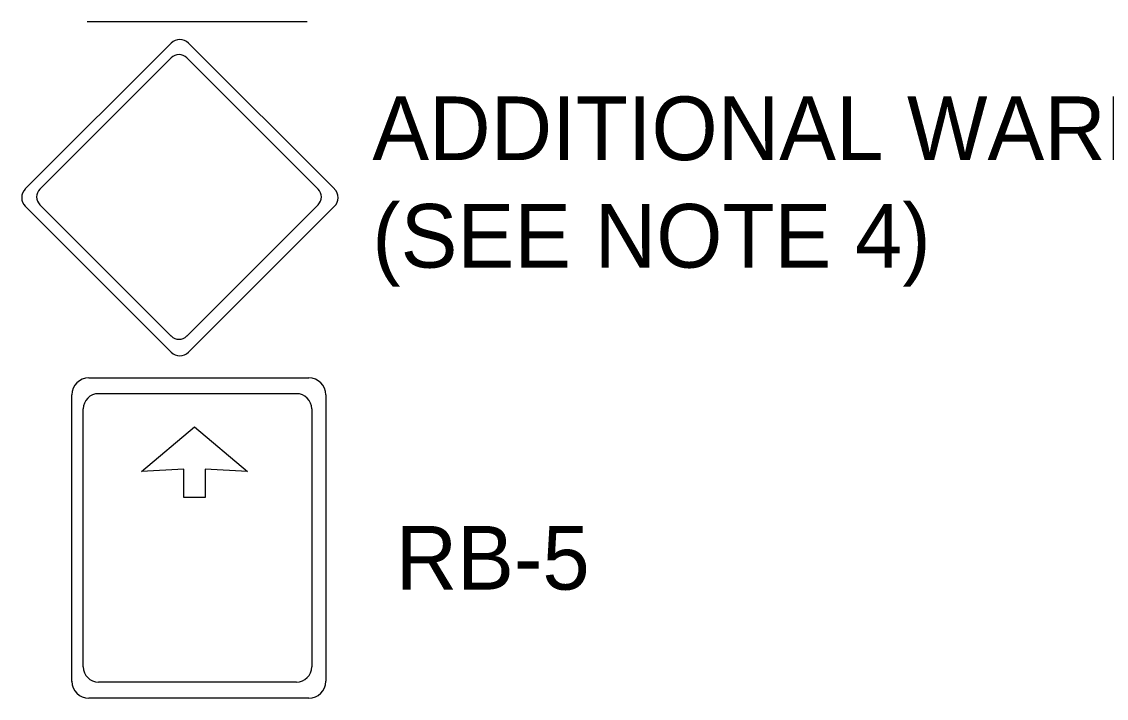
# Model space of a CAD drawing. Extents: x 1372 to 1588, y 125 to 404.
# Drawn here: x 1476.63 to 1513.7, y 179.59 to 202.73 of the extents above; entities that cross this region are included whole.
import ezdxf

# ---------------------------------------------------------------- set-up
doc = ezdxf.new("R2010")
doc.units = 0
doc.layers.add('Level 10', color=7, linetype='Continuous')
doc.layers.add('Level 44', color=7, linetype='Continuous')

msp = doc.modelspace()

# ---------------------------------------------------------------- linework, layer by layer
at = {"layer": 'Level 44'}
for p, q in [((1486.366, 202.729), (1478.871, 202.729)), ((1486.366, 202.729), (1478.871, 202.729)), ((1486.388, 202.728), (1478.872, 202.728)), ((1481.744, 201.993), (1476.75, 197.007)), ((1487.321, 197.007), (1482.334, 201.993)), ((1477.249, 197.003), (1481.744, 201.491)), ((1482.274, 201.491), (1486.763, 197.003)), ((1476.75, 196.414), (1481.744, 191.422)), ((1476.753, 196.414), (1476.75, 196.414)), ((1481.744, 191.977), (1477.249, 196.469)), ((1486.763, 196.469), (1482.274, 191.977)), ((1482.334, 191.422), (1487.321, 196.414)), ((1478.927, 190.549), (1486.445, 190.549)), ((1478.348, 180.17), (1478.348, 189.969)), ((1479.256, 190.008), (1486.022, 190.008)), ((1487.026, 189.969), (1487.026, 180.17)), ((1478.735, 180.666), (1478.735, 189.486)), ((1486.545, 189.486), (1486.545, 180.666)), ((1478.735, 180.664), (1478.735, 180.666)), ((1478.348, 180.167), (1478.348, 180.17)), ((1486.022, 180.143), (1479.256, 180.143)), ((1486.445, 179.587), (1478.927, 179.587))]:
    msp.add_line(p, q, dxfattribs=at)
msp.add_lwpolyline([(1480.721, 187.345), (1482.536, 188.873), (1484.351, 187.345), (1482.899, 187.422), (1482.899, 186.454), (1482.173, 186.454), (1482.173, 187.422)], close=True, dxfattribs=at)
for centre, radius, start, end in [((1482.037, 201.699), 0.418, 45, 135), ((1482.008, 201.226), 0.376, 45, 135), ((1477.048, 196.71), 0.418, 135, 225), ((1477.517, 196.735), 0.376, 135, 225), ((1486.498, 196.735), 0.376, 315, 45), ((1487.027, 196.71), 0.418, 315, 45), ((1482.008, 192.245), 0.376, 225, 315), ((1482.037, 191.72), 0.418, 225, 315), ((1478.928, 189.968), 0.58, 90, 180), ((1486.445, 189.968), 0.58, 360, 90), ((1479.257, 189.484), 0.522, 90, 180), ((1486.022, 189.484), 0.522, 360, 90), ((1479.257, 180.664), 0.522, 180, 270), ((1486.022, 180.664), 0.522, 270, 360), ((1478.928, 180.168), 0.58, 180, 270), ((1486.445, 180.168), 0.58, 270, 360)]:
    msp.add_arc(centre, radius, start, end, dxfattribs=at)

# ---------------------------------------------------------------- texts
at = {"layer": 'Level 10'}
for s, height, p in [('ADDITIONAL WARNING SIGNS AS REQUIRED', 2.17699, (1488.615, 197.994)), ('(SEE NOTE 4)', 2.17699, (1488.614, 194.317)), ('RB-5', 2.1774, (1489.413, 183.305))]:
    msp.add_text(s, height=height, rotation=360, dxfattribs=at).set_placement(p)

doc.saveas('drawing.dxf')
